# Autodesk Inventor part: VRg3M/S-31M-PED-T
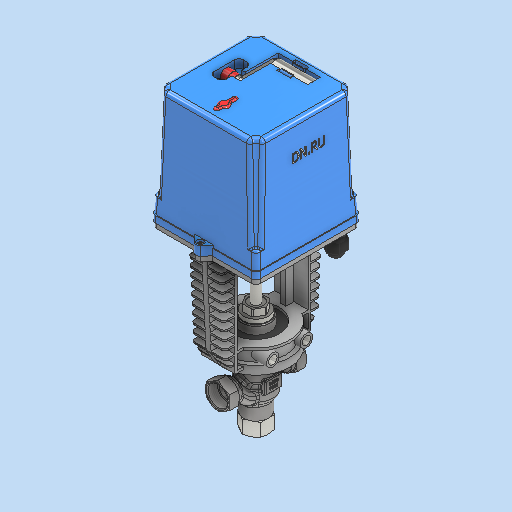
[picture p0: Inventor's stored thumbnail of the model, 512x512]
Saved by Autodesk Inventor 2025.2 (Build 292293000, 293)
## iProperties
Created: 2026-04
Part Number: VRg3M/S-31M-PED-T
Material: Типовые
Description: D230-11264
Document SubType Name: Modeling
Designer: DN.RU
Mass: 3100 g
Surface Area: 2061.72 cm^2
Volume: 2399.13 cm^3
Density: 1.29213 g/cm^3
Appearance: По умолчанию
Company: DN.RU
Title: Клапан регулирующий трехходовой Ду20 Ру25
Author: DN.RU
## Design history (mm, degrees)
derived "Сборка.iam"
node "Твердое тело1"
node "Деталь 1.ipt:1"
node "Деталь 2.ipt:1"
node "Деталь 3.ipt:1"
node "AS 1421 засверленный конец - метрическая M10 x 12 засверленн"
node "AS 1420 - метрическая M5 x 10:1"
node "AS 1420 - метрическая M5 x 10:2"
node "AS 1427 H - метрическая M3 x 8:1"
node "AS 1427 H - метрическая M3 x 8:2"
